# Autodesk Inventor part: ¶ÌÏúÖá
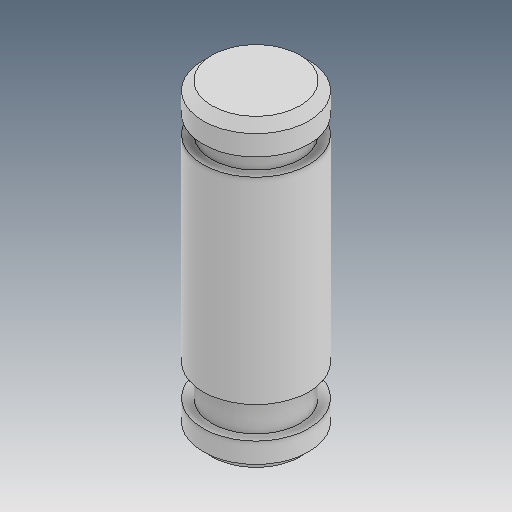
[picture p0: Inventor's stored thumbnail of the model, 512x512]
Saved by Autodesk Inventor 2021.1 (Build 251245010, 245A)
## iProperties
Created: 2019-04
Part Number: ¶ÌÏúÖá
Material: Ogólny
Document SubType Name: Modeling
Designer: user
Density: 1 g/cm^3
Appearance: Domyślna
Author: user
Revision Number: ÈÎºÎ
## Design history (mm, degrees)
feature "ÊäÈë1"
node "Bryła1"
